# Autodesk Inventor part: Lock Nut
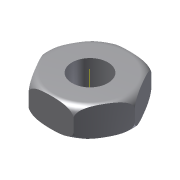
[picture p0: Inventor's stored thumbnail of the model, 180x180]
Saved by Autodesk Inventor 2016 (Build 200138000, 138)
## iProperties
Created: 2009-04
Part Number: Lock Nut
Document SubType Name: Modeling
Designer: Sham
Density: 1 g/cm^3
Material: Generic
Appearance: Default
Author: Sham
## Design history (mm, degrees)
sketch "Sketch1"
  geometry: L1 (7.5, 12.99)-(15, 0); L2 (15, 0)-(7.5, -12.99); L3 (7.5, -12.99)-(-7.5, -12.99); L4 (-7.5, -12.99)-(-15, 0); L5 (-15, 0)-(-7.5, 12.99); L6 (-7.5, 12.99)-(7.5, 12.99); C1 r 6 at (0, 0); 1 further point
  constraints: 12 end point, 1 centre point, 1 coincident, 13 other
  dimensions: "d0" = 30 distance of L1.end L4.end; "d1" = 12 diameter of C1
extrude "Extrusion1" new body sketch "Sketch1" distance "d2" = 10; taper "d3" = 0 deg
sketch "Sketch2"
  geometry: L1 (-12, 0)-(-12, -0.022); L2 (-15, 7)-(-15, 3); L3 (0, -2.87)-(0, 12.87) reference; A1 r 3 centre (-12, 7) between (-12, 10) and (-15, 7); A2 r 3 centre (-12, 3) between (-15, 3) and (-12, 0)
  constraints: 4 end point, 4 point on circle, 2 centre point, 1 tangent
revolve "Revolution1" sketch "Sketch2" stored, may be unused: angle "d7" = 90 deg
body "Solid1"
other parameters: "d6" = 90 deg
